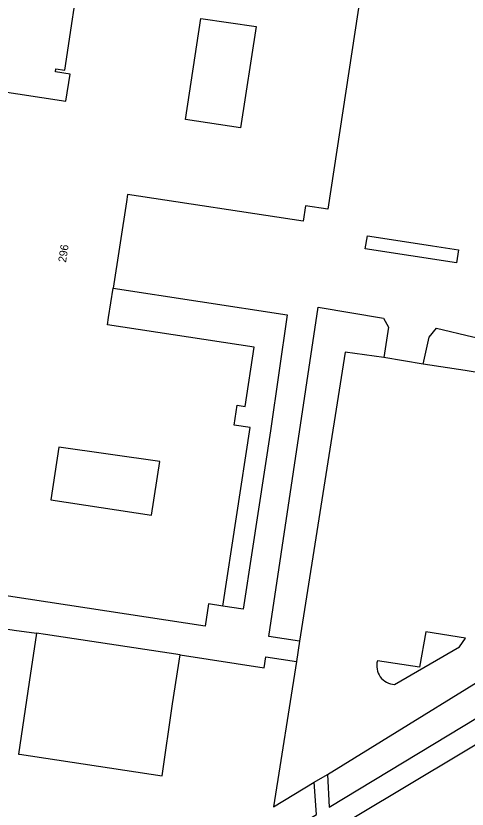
# Model space of a CAD drawing. Extents: x 161486 to 162249, y 379484 to 380829.
# Drawn here: x 162079 to 162135.4, y 380144.1 to 380243.2 of the extents above; entities that cross this region are included whole.
import ezdxf

# ---------------------------------------------------------------- set-up
doc = ezdxf.new("R2010")
doc.units = 0
for name, color, linetype in [('IMGEO_Pand', 7, 'Continuous'), ('IMGEO_Pand_nummerreeks', 7, 'Continuous'), ('IMGEO_Parkeervlak_open', 7, 'Continuous'), ('IMGEO_Rijbaan_lokaal_open', 7, 'Continuous'), ('IMGEO_Voetpad_open', 7, 'Continuous')]:
    doc.layers.add(name, color=color, linetype=linetype)

msp = doc.modelspace()

# ---------------------------------------------------------------- linework, layer by layer
at = {"layer": 'IMGEO_Pand'}
for points in [[(162068.874, 380245.857), (162067.823, 380238.988), (162067.25, 380235.238), (162085.279, 380232.48), (162085.799, 380235.878), (162083.984, 380236.156), (162084.04, 380236.524), (162085.139, 380236.356), (162087.198, 380250)], [(162122.492, 380248.527), (162117.979, 380219.019), (162115.204, 380219.443), (162114.908, 380217.508), (162092.985, 380220.861), (162092.842, 380219.925), (162091.174, 380209.143)], [(162102.132, 380242.835), (162109.031, 380241.818), (162107.093, 380229.151), (162100.215, 380230.203), (162102.132, 380242.835)], [(162104.862, 380169.437), (162108.274, 380191.74), (162106.302, 380192.042), (162106.684, 380194.541), (162107.663, 380194.391), (162108.792, 380201.77), (162090.469, 380204.573), (162090.607, 380205.475), (162091.174, 380209.143)], [(162104.862, 380169.437), (162103.084, 380169.709), (162102.658, 380166.921), (162073.156, 380171.434), (162073.58, 380174.205), (162071.698, 380174.493), (162075.047, 380196.386), (162074.11, 380196.529), (162074.165, 380196.884), (162076.03, 380196.598), (162076.55, 380199.996), (162058.427, 380202.768), (162057.918, 380199.44), (162059.722, 380199.164), (162059.664, 380198.786), (162058.739, 380198.928), (162057.341, 380189.79)], [(162083.4, 380182.735), (162095.987, 380180.81), (162097.013, 380187.517), (162084.403, 380189.294), (162083.4, 380182.735)]]:
    msp.add_lwpolyline(points, dxfattribs=at)
at = {"layer": 'IMGEO_Parkeervlak_open'}
for points in [[(162124.98, 380200.499), (162120.136, 380201.151), (162114.469, 380165.057)], [(162140.073, 380198.041), (162135.137, 380198.884), (162129.91, 380199.65)], [(162117.941, 380148.426), (162145.458, 380165.392), (162150.33, 380196.471), (162145.089, 380197.276)], [(162081.621, 380166.059), (162080.691, 380159.947), (162079.356, 380150.968), (162079.499, 380150.946), (162097.294, 380148.237), (162098.616, 380157.254), (162099.543, 380163.341)], [(162130.223, 380166.231), (162129.44, 380161.803), (162124.184, 380162.631)], [(162126.322, 380159.649), (162134.44, 380164.348), (162135.162, 380165.432), (162130.223, 380166.231)], [(162114.071, 380162.523), (162111.222, 380144.379), (162116.291, 380147.473)]]:
    msp.add_lwpolyline(points, dxfattribs=at)
msp.add_arc((162126.457, 380162.003), 2.358, 164.5642, 266.71446, dxfattribs=at)
at = {"layer": 'IMGEO_Rijbaan_lokaal_open'}
for points in [[(162122.927, 380215.7), (162129.746, 380214.645), (162131.079, 380214.416), (162134.291, 380213.936), (162134.038, 380212.305), (162122.674, 380214.07), (162122.927, 380215.7)], [(162091.174, 380209.143), (162112.9, 380205.802), (162110.841, 380191.347), (162108.553, 380176.388), (162107.429, 380169.044), (162104.862, 380169.437)], [(162114.469, 380165.057), (162110.623, 380165.66), (162116.803, 380206.772), (162124.937, 380205.402), (162125.557, 380204.273), (162124.98, 380200.499)], [(162129.91, 380199.65), (162130.666, 380203.039), (162131.554, 380204.169), (162136.093, 380203.084), (162139.89, 380202.237), (162140.631, 380200.979), (162140.073, 380198.041)], [(162129.91, 380199.65), (162124.98, 380200.499)], [(162071.066, 380167.629), (162078.829, 380166.441), (162081.621, 380166.059)], [(162099.543, 380163.341), (162082.745, 380165.905), (162081.621, 380166.059)], [(162114.469, 380165.057), (162114.071, 380162.523)], [(162099.543, 380163.341), (162110.034, 380161.739), (162110.238, 380163.098), (162114.071, 380162.523)]]:
    msp.add_lwpolyline(points, dxfattribs=at)
at = {"layer": 'IMGEO_Voetpad_open'}
for points in [[(162117.941, 380148.426), (162118.168, 380144.356), (162147.853, 380162.262)], [(162148.972, 380159.764), (162141.241, 380154.993), (162101.852, 380131.396), (162100.821, 380132.884), (162084.164, 380121.943)], [(162116.291, 380147.473), (162117.941, 380148.426)], [(162113.044, 380141.292), (162116.59, 380143.424), (162116.291, 380147.473)]]:
    msp.add_lwpolyline(points, dxfattribs=at)

# ---------------------------------------------------------------- texts
at = {"layer": 'IMGEO_Pand_nummerreeks'}
msp.add_text('296', height=1, rotation=81.30271, dxfattribs=at).set_placement((162085.297, 380212.313))

doc.saveas('drawing.dxf')
